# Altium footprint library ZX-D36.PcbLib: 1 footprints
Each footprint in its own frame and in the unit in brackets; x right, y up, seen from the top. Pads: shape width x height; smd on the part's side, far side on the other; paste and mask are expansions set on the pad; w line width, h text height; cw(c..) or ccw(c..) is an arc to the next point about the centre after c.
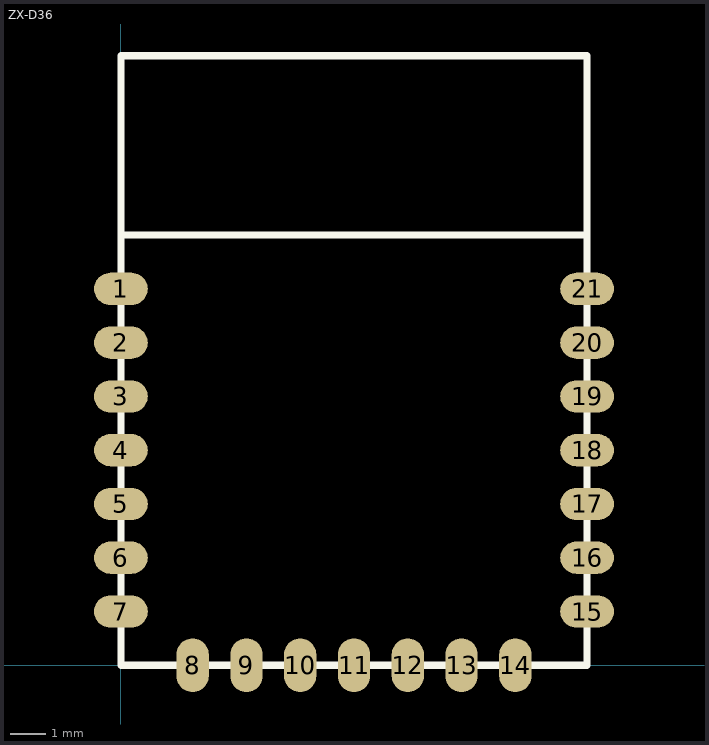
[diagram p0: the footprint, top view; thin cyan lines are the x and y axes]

## ZX-D36 [mm]
pads (21):
  oval 1.5x0.9 smd: 1(0,10.5) 2(0,9) 3(0,7.5) 4(0,6) 5(0,4.5) 6(0,3) 7(0,1.5) 15(13,1.5) 16(13,3) 17(13,4.5) 18(13,6) 19(13,7.5) 20(13,9) 21(13,10.5)
  oval 0.9x1.5 smd: 8(2,0) 9(3.5,0) 10(5,0) 11(6.5,0) 12(8,0) 13(9.5,0) 14(11,0)
Top Overlay:
  lines w0.2: 0,12 13,12 ; 0,0 0,17 13,17 13,0 0,0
